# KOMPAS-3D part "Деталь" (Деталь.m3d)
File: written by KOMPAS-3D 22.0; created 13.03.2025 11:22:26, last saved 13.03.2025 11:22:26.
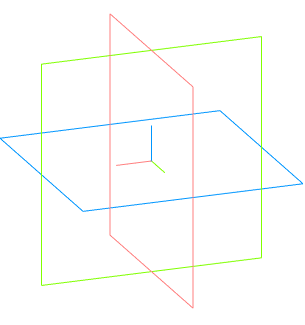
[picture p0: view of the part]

Document properties: Автор: Пользователь Windows; Полное имя файла: C:\Users\Student\Documents\Картошечка\База Сабнатика\Деталь.m3d

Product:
- Part/product: Деталь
